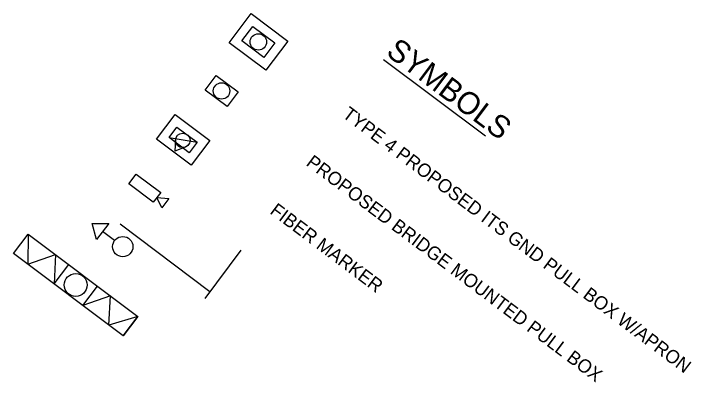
# Model space of a CAD drawing. Extents: x 626494 to 628584, y 365986 to 369269.
# Drawn here: x 628125.5 to 628307.6, y 368124.4 to 368223.6 of the extents above; entities that cross this region are included whole.
import ezdxf

# ---------------------------------------------------------------- set-up
doc = ezdxf.new("R2010")
doc.units = 0
for name, color, linetype in [('R_Shade Frontage Road', 7, 'Continuous'), ('R_Survey Control', 7, 'Continuous'), ('USACE_Easement', 7, 'Continuous')]:
    doc.layers.add(name, color=color, linetype=linetype)

msp = doc.modelspace()

# ---------------------------------------------------------------- linework, layer by layer
at = {"layer": 'R_Shade Frontage Road'}
msp.add_line((628224.92, 368211.2), (628252.27, 368190.66), dxfattribs=at)
at = {"layer": 'R_Survey Control'}
for p, q in [((628154.1, 368166.99), (628178.26, 368148.85)), ((628152.65, 368162.55), (628149.42, 368164.98)), ((628186.58, 368159.91), (628176.85, 368146.96))]:
    msp.add_line(p, q, dxfattribs=at)
for points in [[(628168.88, 368196.41), (628178.22, 368189.39), (628173.26, 368182.79), (628163.92, 368189.81)], [(628169.41, 368193.06), (628174.86, 368188.97), (628172.72, 368186.11), (628167.27, 368190.21)], [(628167.28, 368190.23), (628174.86, 368188.97), (628172.72, 368186.11)], [(628158.46, 368180.42), (628165.03, 368175.49), (628163.02, 368172.81), (628156.45, 368177.74)], [(628164.03, 368174.15), (628167.22, 368173.84), (628165.34, 368171.34)], [(628151.06, 368167.16), (628147.78, 368162.8), (628146.58, 368167.1)], [(628129.44, 368164.28), (628158.91, 368142.14), (628154.98, 368136.9), (628125.5, 368159.03)]]:
    msp.add_lwpolyline(points, close=True, dxfattribs=at)
for points in [[(628125.5, 368159.03), (628129.44, 368164.28), (628129.35, 368156.14), (628136.77, 368158.77), (628136.37, 368150.87), (628140.31, 368156.11)], [(628154.98, 368136.9), (628158.91, 368142.14), (628151.12, 368139.79), (628151.58, 368147.65), (628144.1, 368145.06), (628148.04, 368150.31)]]:
    msp.add_lwpolyline(points, dxfattribs=at)
for centre, radius in [((628154.83, 368160.9), 2.73), ((628142.2, 368150.59), 3.06)]:
    msp.add_circle(centre, radius, dxfattribs=at)
at = {"layer": 'USACE_Easement'}
for p in [(628169.03, 368189.6), (628171.65, 368187.64)]:
    msp.add_line(p, (628168.8, 368186.58), dxfattribs=at)
for points in [[(628189.32, 368223.57), (628199.15, 368216.18), (628193.24, 368208.31), (628183.41, 368215.7)], [(628189.81, 368220.12), (628195.71, 368215.69), (628192.75, 368211.76), (628186.85, 368216.19)], [(628179.91, 368206.94), (628185.81, 368202.51), (628182.86, 368198.58), (628176.95, 368203.01)]]:
    msp.add_lwpolyline(points, close=True, dxfattribs=at)
for centre, radius in [((628191.28, 368215.94), 2.21), ((628181.38, 368202.76), 2.21), ((628170.97, 368189.46), 1.95)]:
    msp.add_circle(centre, radius, dxfattribs=at)

# ---------------------------------------------------------------- texts
at = {"layer": 'R_Shade Frontage Road'}
for s, height, p in [('SYMBOLS', 6, (628225.29, 368212.6)), ('TYPE 4 PROPOSED ITS GND PULL BOX W/APRON', 3.6, (628213.6, 368195.9)), ('PROPOSED BRIDGE MOUNTED PULL BOX', 3.6, (628203.87, 368182.94))]:
    msp.add_text(s, height=height, rotation=323.0968, dxfattribs=at).set_placement(p)
at = {"layer": 'USACE_Easement'}
msp.add_text('FIBER MARKER', height=3.6, rotation=323.0968, dxfattribs=at).set_placement((628194.14, 368169.99))

doc.saveas('drawing.dxf')
